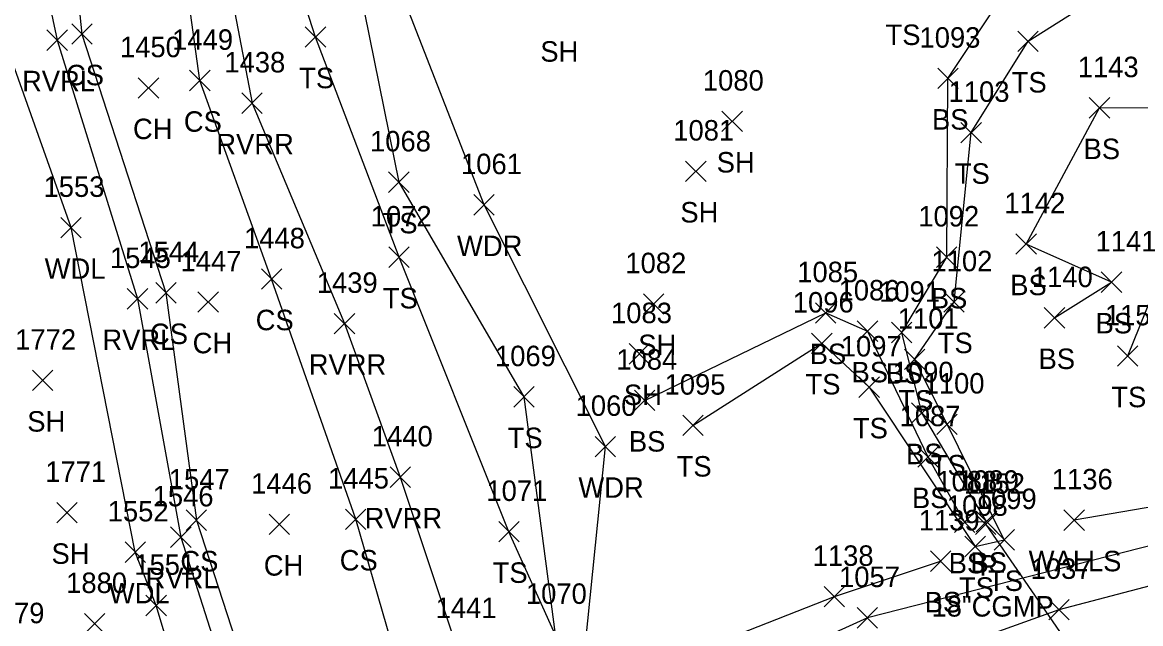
# Model space of a CAD drawing. Extents: x 1621633 to 1624015, y 417863 to 420979.
# Drawn here: x 1621947.4 to 1622056.7, y 418125.3 to 418184 of the extents above; entities that cross this region are included whole.
import ezdxf

# ---------------------------------------------------------------- set-up
doc = ezdxf.new("R2010")
doc.units = 0
for name, color, linetype in [('D_A', 7, 'Continuous'), ('D_C', 7, 'Continuous'), ('D_I', 7, 'Continuous'), ('D_TIC', 7, 'Continuous'), ('DCP', 7, 'Continuous'), ('L_A', 7, 'Continuous'), ('L_I', 7, 'Continuous'), ('L_TIC', 7, 'Continuous'), ('LAWA', 7, 'Continuous'), ('LAWE', 7, 'Continuous'), ('LELB', 7, 'Continuous'), ('LWS', 7, 'Continuous'), ('P_I', 7, 'Continuous'), ('P_TIC', 7, 'Continuous'), ('PEU', 7, 'Continuous')]:
    doc.layers.add(name, color=color, linetype=linetype)

msp = doc.modelspace()

# ---------------------------------------------------------------- linework, layer by layer
at = {"layer": 'D_TIC'}
for points in [[(1622040.57, 418134.01), (1622042.57, 418136.01)], [(1622042.57, 418134.01), (1622040.57, 418136.01)]]:
    msp.add_lwpolyline(points, dxfattribs=at)
at = {"layer": 'DCP'}
msp.add_lwpolyline([(1622041.57, 418135.01), (1622064.54, 418101.68)], dxfattribs=at)
at = {"layer": 'L_TIC'}
for points in [[(1621949.84, 418181.3), (1621951.84, 418183.3)], [(1621951.84, 418181.3), (1621949.84, 418183.3)], [(1621952.26, 418181.89), (1621954.26, 418183.89)], [(1621954.26, 418181.89), (1621952.26, 418183.89)], [(1621975.08, 418181.6), (1621977.08, 418183.6)], [(1621977.08, 418181.6), (1621975.08, 418183.6)], [(1622044.7, 418181.18), (1622046.7, 418183.18)], [(1622046.7, 418181.18), (1622044.7, 418183.18)], [(1621963.78, 418177.35), (1621965.78, 418179.35)], [(1621965.78, 418177.35), (1621963.78, 418179.35)], [(1622036.88, 418177.56), (1622038.88, 418179.56)], [(1622038.88, 418177.56), (1622036.88, 418179.56)], [(1621958.76, 418176.63), (1621960.76, 418178.63)], [(1621960.76, 418176.63), (1621958.76, 418178.63)], [(1621968.88, 418175.14), (1621970.88, 418177.14)], [(1621970.88, 418175.14), (1621968.88, 418177.14)], [(1622051.69, 418174.68), (1622053.69, 418176.68)], [(1622053.69, 418174.68), (1622051.69, 418176.68)], [(1622015.79, 418173.37), (1622017.79, 418175.37)], [(1622017.79, 418173.37), (1622015.79, 418175.37)], [(1622039.15, 418172.27), (1622041.15, 418174.27)], [(1622041.15, 418172.27), (1622039.15, 418174.27)], [(1622012.24, 418168.49), (1622014.24, 418170.49)], [(1622014.24, 418168.49), (1622012.24, 418170.49)], [(1621983.23, 418167.43), (1621985.23, 418169.43)], [(1621985.23, 418167.43), (1621983.23, 418169.43)], [(1621991.55, 418165.21), (1621993.55, 418167.21)], [(1621993.55, 418165.21), (1621991.55, 418167.21)], [(1621951.2, 418162.99), (1621953.2, 418164.99)], [(1621953.2, 418162.99), (1621951.2, 418164.99)], [(1622044.52, 418161.39), (1622046.52, 418163.39)], [(1622046.52, 418161.39), (1622044.52, 418163.39)], [(1621983.25, 418160.1), (1621985.25, 418162.1)], [(1621985.25, 418160.1), (1621983.25, 418162.1)], [(1622036.76, 418160.1), (1622038.76, 418162.1)], [(1622038.76, 418160.1), (1622036.76, 418162.1)], [(1621970.8, 418157.97), (1621972.8, 418159.97)], [(1621972.8, 418157.97), (1621970.8, 418159.97)], [(1622052.86, 418157.66), (1622054.86, 418159.66)], [(1622054.86, 418157.66), (1622052.86, 418159.66)], [(1621960.47, 418156.62), (1621962.47, 418158.62)], [(1621962.47, 418156.62), (1621960.47, 418158.62)], [(1621957.69, 418156.04), (1621959.69, 418158.04)], [(1621959.69, 418156.04), (1621957.69, 418158.04)], [(1621964.59, 418155.72), (1621966.59, 418157.72)], [(1621966.59, 418155.72), (1621964.59, 418157.72)], [(1622008.13, 418155.54), (1622010.13, 418157.54)], [(1622010.13, 418155.54), (1622008.13, 418157.54)], [(1622037.47, 418155.73), (1622039.47, 418157.73)], [(1622039.47, 418155.73), (1622037.47, 418157.73)], [(1622024.93, 418154.66), (1622026.93, 418156.66)], [(1622026.93, 418154.66), (1622024.93, 418156.66)], [(1622047.29, 418154.18), (1622049.29, 418156.18)], [(1622049.29, 418154.18), (1622047.29, 418156.18)], [(1621977.91, 418153.62), (1621979.91, 418155.62)], [(1621979.91, 418153.62), (1621977.91, 418155.62)], [(1622029.02, 418152.88), (1622031.02, 418154.88)], [(1622031.02, 418152.88), (1622029.02, 418154.88)], [(1622032.36, 418152.75), (1622034.36, 418154.75)], [(1622034.36, 418152.75), (1622032.36, 418154.75)], [(1622024.55, 418151.7), (1622026.55, 418153.7)], [(1622026.55, 418151.7), (1622024.55, 418153.7)], [(1622006.73, 418150.66), (1622008.73, 418152.66)], [(1622008.73, 418150.66), (1622006.73, 418152.66)], [(1622033.62, 418150.12), (1622035.62, 418152.12)], [(1622035.62, 418150.12), (1622033.62, 418152.12)], [(1622054.43, 418150.45), (1622056.43, 418152.45)], [(1622056.43, 418150.45), (1622054.43, 418152.45)], [(1621948.43, 418148.07), (1621950.43, 418150.07)], [(1621950.43, 418148.07), (1621948.43, 418150.07)], [(1622029.18, 418147.41), (1622031.18, 418149.41)], [(1622031.18, 418147.41), (1622029.18, 418149.41)], [(1621995.45, 418146.46), (1621997.45, 418148.46)], [(1621997.45, 418146.46), (1621995.45, 418148.46)], [(1622007.25, 418146.12), (1622009.25, 418148.12)], [(1622009.25, 418146.12), (1622007.25, 418148.12)], [(1622034.33, 418144.89), (1622036.33, 418146.89)], [(1622036.33, 418144.89), (1622034.33, 418146.89)], [(1622011.96, 418143.68), (1622013.96, 418145.68)], [(1622013.96, 418143.68), (1622011.96, 418145.68)], [(1622036.79, 418143.79), (1622038.79, 418145.79)], [(1622038.79, 418143.79), (1622036.79, 418145.79)], [(1622003.41, 418141.61), (1622005.41, 418143.61)], [(1622005.41, 418141.61), (1622003.41, 418143.61)], [(1622034.92, 418140.6), (1622036.92, 418142.6)], [(1622036.92, 418140.6), (1622034.92, 418142.6)], [(1621983.37, 418138.62), (1621985.37, 418140.62)], [(1621985.37, 418138.62), (1621983.37, 418140.62)], [(1621950.81, 418135.16), (1621952.81, 418137.16)], [(1621952.81, 418135.16), (1621950.81, 418137.16)], [(1621963.44, 418134.42), (1621965.44, 418136.42)], [(1621965.44, 418134.42), (1621963.44, 418136.42)], [(1621979.01, 418134.51), (1621981.01, 418136.51)], [(1621981.01, 418134.51), (1621979.01, 418136.51)], [(1622049.21, 418134.43), (1622051.21, 418136.43)], [(1622051.21, 418134.43), (1622049.21, 418136.43)], [(1621971.54, 418134.01), (1621973.54, 418136.01)], [(1621973.54, 418134.01), (1621971.54, 418136.01)], [(1621993.98, 418133.3), (1621995.98, 418135.3)], [(1621995.98, 418133.3), (1621993.98, 418135.3)], [(1622038.51, 418134.23), (1622040.51, 418136.23)], [(1622040.51, 418134.23), (1622038.51, 418136.23)], [(1622040.64, 418134.29), (1622042.64, 418136.29)], [(1622042.64, 418134.29), (1622040.64, 418136.29)], [(1621961.92, 418132.77), (1621963.92, 418134.77)], [(1621963.92, 418132.77), (1621961.92, 418134.77)], [(1622042.38, 418132.51), (1622044.38, 418134.51)], [(1622044.38, 418132.51), (1622042.38, 418134.51)], [(1621957.47, 418131.3), (1621959.47, 418133.3)], [(1621959.47, 418131.3), (1621957.47, 418133.3)], [(1622039.54, 418131.85), (1622041.54, 418133.85)], [(1622041.54, 418131.85), (1622039.54, 418133.85)], [(1622036.16, 418130.42), (1622038.16, 418132.42)], [(1622038.16, 418130.42), (1622036.16, 418132.42)], [(1622025.78, 418126.96), (1622027.78, 418128.96)], [(1622027.78, 418126.96), (1622025.78, 418128.96)], [(1621959.51, 418126.09), (1621961.51, 418128.09)], [(1621961.51, 418126.09), (1621959.51, 418128.09)], [(1622029.01, 418124.89), (1622031.01, 418126.89)], [(1622031.01, 418124.89), (1622029.01, 418126.89)], [(1621953.5, 418124.31), (1621955.5, 418126.31)], [(1621955.5, 418124.31), (1621953.5, 418126.31)]]:
    msp.add_lwpolyline(points, dxfattribs=at)
at = {"layer": 'LAWA'}
for points in [[(1622320.21, 418157.08), (1622282.22, 418156.15), (1622251.71, 418155.08), (1622223.6, 418155.09), (1622209.11, 418155.31), (1622180.88, 418152.89), (1622152.12, 418150.87), (1622117.37, 418144.74), (1622094.14, 418141.69), (1622062.96, 418134.28), (1622030.01, 418125.89), (1622002.09, 418113.22), (1622001.94, 418118.19), (1622004.41, 418142.61), (1621992.55, 418166.21), (1621982.92, 418190.96), (1621974.22, 418213.57), (1621987.21, 418225.09), (1622016.71, 418238.58), (1622052.18, 418242.59)], [(1621964.88, 418112.57), (1621960.51, 418127.09), (1621958.47, 418132.3), (1621952.2, 418163.99), (1621942.42, 418191.54), (1621933.84, 418203.58)]]:
    msp.add_lwpolyline(points, dxfattribs=at)
at = {"layer": 'LAWE'}
for points in [[(1622333.17, 418232.98), (1622304.92, 418224.43), (1622278.58, 418222.6), (1622250.59, 418234.06), (1622231.09, 418250.9), (1622207.09, 418257.63), (1622185.14, 418265.61), (1622157.85, 418271.29), (1622128.42, 418279.11), (1622109.18, 418281.03), (1622103.42, 418276.53), (1622081.07, 418269.59), (1622054.89, 418266.85), (1622024.68, 418262.78), (1621999.35, 418261.34), (1621980.1, 418259.35), (1621959.54, 418247.53), (1621949.11, 418230.91), (1621945.67, 418206.62), (1621950.84, 418182.3), (1621958.69, 418157.04), (1621962.92, 418133.77), (1621970.23, 418110.89)], [(1622323.31, 418180.93), (1622300.82, 418170.32), (1622276.31, 418168.44), (1622241.72, 418167.29), (1622221.82, 418173.51), (1622205.88, 418194.82), (1622185.97, 418220.63), (1622162.23, 418235.42), (1622129.82, 418241.7), (1622106.38, 418246.35), (1622101.43, 418250.25), (1622073.09, 418248.58), (1622043.82, 418244.16), (1622014.93, 418241.31), (1621989.87, 418234.25), (1621972.68, 418220.99), (1621964.49, 418204.33), (1621969.88, 418176.14), (1621978.91, 418154.62), (1621984.37, 418139.62), (1621989.94, 418122.86), (1621991.15, 418115.14)]]:
    msp.add_lwpolyline(points, dxfattribs=at)
at = {"layer": 'LELB'}
for points in [[(1621986.07, 418114.57), (1621980.01, 418135.51), (1621971.8, 418158.97), (1621964.78, 418178.35), (1621962.01, 418198.43), (1621960.3, 418210.78), (1621971.3, 418225.2), (1621983.84, 418236.14), (1622007.18, 418245.45), (1622025.65, 418246.51), (1622054.04, 418255.07), (1622065.32, 418256.15)], [(1621951.89, 418230.38), (1621950.81, 418206.6), (1621953.26, 418182.89), (1621961.47, 418157.62), (1621964.44, 418135.42), (1621972.58, 418110.48)], [(1622012.96, 418144.68), (1622025.55, 418152.7), (1622030.18, 418148.41), (1622040.54, 418132.85), (1622043.38, 418133.51), (1622037.79, 418144.79), (1622034.62, 418151.12), (1622038.47, 418156.73), (1622040.15, 418173.27), (1622045.7, 418182.18), (1622058.58, 418190.33), (1622063.65, 418207.42), (1622064.55, 418215.49), (1622074.9, 418223.54), (1622095.34, 418218.88), (1622118.02, 418219.75), (1622146.4, 418210.35), (1622169.6, 418199.38), (1622194.43, 418184.07), (1622206.1, 418163.37)], [(1621971.1, 418202.04), (1621979.4, 418192.23), (1621984.23, 418168.43), (1621996.45, 418147.46), (1621999.49, 418124.25), (1621994.98, 418134.3), (1621984.25, 418161.1), (1621976.08, 418182.6), (1621971.89, 418195.68)], [(1622008.25, 418147.12), (1622025.93, 418155.66), (1622030.02, 418153.88), (1622035.92, 418141.6), (1622039.51, 418135.23), (1622041.64, 418135.29), (1622035.33, 418145.89), (1622033.36, 418153.75), (1622037.76, 418161.1), (1622037.88, 418178.56), (1622049.21, 418195.59)], [(1622048.29, 418155.18), (1622053.86, 418158.66), (1622045.52, 418162.39), (1622052.69, 418175.68), (1622078.7, 418175.76), (1622095.64, 418168.67), (1622097.55, 418156.67)], [(1622080.75, 418159.24), (1622065.92, 418164.54), (1622059.56, 418161.67), (1622055.43, 418151.45)], [(1622006.41, 418119.96), (1622026.78, 418127.96), (1622037.16, 418131.42)]]:
    msp.add_lwpolyline(points, dxfattribs=at)
at = {"layer": 'LWS'}
msp.add_lwpolyline([(1622176.03, 418157.31), (1622150.73, 418155.55), (1622127.26, 418149.05), (1622105.64, 418146.5), (1622090.95, 418143.6), (1622069.97, 418138.82), (1622050.21, 418135.43)], dxfattribs=at)
at = {"layer": 'P_TIC'}
for points in [[(1622047.73, 418125.69), (1622049.73, 418127.69)], [(1622049.73, 418125.69), (1622047.73, 418127.69)]]:
    msp.add_lwpolyline(points, dxfattribs=at)
at = {"layer": 'PEU'}
msp.add_lwpolyline([(1622194.17, 418133.58), (1622165.78, 418130.65), (1622135.81, 418126.42), (1622106.7, 418121.83), (1622082.09, 418116.18), (1622052.81, 418106.54), (1622024.04, 418100.48), (1621997.92, 418097.2), (1621996.78, 418104.27), (1621996.21, 418110.35), (1622021.08, 418116.79), (1622048.73, 418126.69), (1622081.22, 418135.22), (1622108.12, 418139.76), (1622139.72, 418144.66), (1622170.97, 418148.68), (1622202.2, 418150.62)], dxfattribs=at)

# ---------------------------------------------------------------- texts
at = {"layer": 'D_A'}
msp.add_text('P', height=2, dxfattribs=at).set_placement((1622040.95, 418130.01))
at = {"layer": 'D_C'}
msp.add_text('18"CGMP', height=2, dxfattribs=at).set_placement((1622036.27, 418126.01))
at = {"layer": 'D_I'}
msp.add_text('1152', height=2, dxfattribs=at).set_placement((1622039.45, 418138.01))
at = {"layer": 'L_A'}
for s, p in [('TS', (1622031.78, 418181.82)), ('SH', (1621998.05, 418180.19)), ('RVRL', (1621947.41, 418177.3)), ('CS', (1621951.7, 418177.89)), ('TS', (1621974.49, 418177.6)), ('TS', (1622044.11, 418177.18)), ('CH', (1621958.25, 418172.63)), ('CS', (1621963.22, 418173.35)), ('BS', (1622036.32, 418173.56)), ('RVRR', (1621966.39, 418171.14)), ('BS', (1622051.13, 418170.68)), ('SH', (1622015.28, 418169.37)), ('TS', (1622038.55, 418168.27)), ('SH', (1622011.73, 418164.49)), ('TS', (1621982.64, 418163.43)), ('WDR', (1621989.91, 418161.21)), ('WDL', (1621949.62, 418158.99)), ('BS', (1622043.96, 418157.39)), ('TS', (1621982.66, 418156.1)), ('BS', (1622036.2, 418156.1)), ('CS', (1621970.24, 418153.97)), ('BS', (1622052.3, 418153.66)), ('RVRL', (1621955.26, 418152.04)), ('CS', (1621959.91, 418152.62)), ('CH', (1621964.08, 418151.72)), ('SH', (1622007.62, 418151.54)), ('BS', (1622024.37, 418150.66)), ('TS', (1622036.88, 418151.73)), ('RVRR', (1621975.42, 418149.62)), ('BS', (1622046.73, 418150.18)), ('BS', (1622028.46, 418148.88)), ('BS', (1622031.8, 418148.75)), ('TS', (1622023.96, 418147.7)), ('SH', (1622006.22, 418146.66)), ('TS', (1622053.84, 418146.45)), ('TS', (1622033.03, 418146.12)), ('SH', (1621947.92, 418144.07)), ('TS', (1622028.59, 418143.41)), ('TS', (1621994.86, 418142.46)), ('BS', (1622006.7, 418142.12)), ('BS', (1622033.78, 418140.89)), ('TS', (1622036.2, 418139.79)), ('TS', (1622011.37, 418139.68)), ('WDR', (1622001.77, 418137.61)), ('BS', (1622034.36, 418136.6)), ('RVRR', (1621980.88, 418134.62)), ('SH', (1621950.29, 418131.16)), ('CS', (1621962.88, 418130.42)), ('CH', (1621971.03, 418130.01)), ('CS', (1621978.45, 418130.51)), ('BS', (1622037.95, 418130.23)), ('BS', (1622040.08, 418130.29)), ('WALLS', (1622045.76, 418130.43)), ('TS', (1621993.39, 418129.3)), ('RVRL', (1621959.48, 418128.77)), ('TS', (1622038.95, 418127.85)), ('TS', (1622041.79, 418128.51)), ('WDL', (1621955.89, 418127.3)), ('BS', (1622035.6, 418126.42))]:
    msp.add_text(s, height=2, dxfattribs=at).set_placement(p)
at = {"layer": 'L_I'}
for s, p in [('1449', (1621962.08, 418181.35)), ('1093', (1622035.1, 418181.56)), ('1450', (1621956.98, 418180.63)), ('1438', (1621967.18, 418179.14)), ('1143', (1622050.56, 418178.68)), ('1080', (1622013.93, 418177.37)), ('1103', (1622037.94, 418176.27)), ('1068', (1621981.41, 418171.43)), ('1081', (1622011.04, 418172.49)), ('1061', (1621990.3, 418169.21)), ('1553', (1621949.51, 418166.99)), ('1142', (1622043.39, 418165.39)), ('1072', (1621981.48, 418164.1)), ('1092', (1622034.98, 418164.1)), ('1448', (1621969.1, 418161.97)), ('1141', (1622052.3, 418161.66)), ('1544', (1621958.77, 418160.62)), ('1545', (1621956, 418160.04)), ('1447', (1621962.9, 418159.72)), ('1082', (1622006.36, 418159.54)), ('1102', (1622036.27, 418159.73)), ('1085', (1622023.15, 418158.66)), ('1439', (1621976.21, 418157.62)), ('1140', (1622046.08, 418158.18)), ('1086', (1622027.19, 418156.88)), ('1091', (1622031.15, 418156.75)), ('1096', (1622022.72, 418155.7)), ('1083', (1622004.96, 418154.66)), ('1101', (1622032.98, 418154.12)), ('1150', (1622053.21, 418154.45)), ('1772', (1621946.74, 418152.07)), ('1097', (1622027.41, 418151.41)), ('1069', (1621993.62, 418150.46)), ('1084', (1622005.48, 418150.12)), ('1090', (1622032.48, 418148.89)), ('1095', (1622010.19, 418147.68)), ('1100', (1622035.5, 418147.79)), ('1060', (1622001.5, 418145.61)), ('1087', (1622033.15, 418144.6)), ('1440', (1621981.59, 418142.62)), ('1771', (1621949.68, 418139.16)), ('1547', (1621961.75, 418138.42)), ('1446', (1621969.79, 418138.01)), ('1445', (1621977.31, 418138.51)), ('1088', (1622036.74, 418138.23)), ('1089', (1622038.86, 418138.29)), ('1136', (1622048.03, 418138.43)), ('1546', (1621960.17, 418136.77)), ('1071', (1621992.78, 418137.3)), ('1099', (1622040.6, 418136.51)), ('1098', (1622037.77, 418135.85)), ('1552', (1621955.78, 418135.3)), ('1139', (1622035.03, 418134.42)), ('1551', (1621958.38, 418130.09)), ('1138', (1622024.66, 418130.96)), ('1057', (1622027.24, 418128.89)), ('1880', (1621951.72, 418128.31)), ('1070', (1621996.64, 418127.25)), ('1441', (1621987.82, 418125.86)), ('1879', (1621943.65, 418125.36))]:
    msp.add_text(s, height=2, dxfattribs=at).set_placement(p)
at = {"layer": 'P_I'}
msp.add_text('1037', height=2, dxfattribs=at).set_placement((1622045.96, 418129.69))

doc.saveas('drawing.dxf')
